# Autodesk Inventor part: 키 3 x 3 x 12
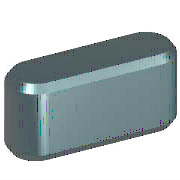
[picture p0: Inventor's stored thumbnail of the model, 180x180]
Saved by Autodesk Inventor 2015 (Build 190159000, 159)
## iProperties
Created: 2012-02
Part Number: 키 3 x 3 x 12
Material: 강철, 연강
Description: 키 및 해당 키홈
Document SubType Name: Modeling
Standard: KS B 1311
Designer: mduedu
Standards Organization: KS
Language: ko-KR
Size Designation: 3 x 3 x 12
Categories: <MemberInstance><Categories><Category DisplayName="샤프트 부품" InternalName="7f7aeb1f-a693-4053-b835-cee3144e0d98" Mnemonic="SHFT"><Category DisplayName="키" Interna
Density: 1 g/cm^3
Appearance: 강철
IsCustomPart: 1
Author: mduedu
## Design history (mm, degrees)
workplane "Work Plane1"
workplane "Work Plane2"
sketch "스케치1"
  geometry: L1 (1.5, 1.5)-(10.5, 1.5); L2 (10.5, -1.5)-(1.5, -1.5); L3 (0, 9.4)-(0, -7.4) reference; L4 (-5, 0)-(30, 0) reference; L5 (12, 0)-(12, 7); A1 r 1.5 centre (1.5, 0) between (1.5, 1.5) and (1.5, -1.5); A2 r 1.5 centre (10.5, 0) between (10.5, -1.5) and (10.5, 1.5)
  constraints: 6 end point, 5 point on circle, 4 tangent, 3 point on line, 2 centre point, 1 horizontal, 1 parallel, 1 perpendicular
  dimensions: "d0" = 1.5 radius of A1 (= 0.5 x PB); "d13" = 1.5 radius of A2 (= 0.5 x PB); "d14" = 12 distance between parallel lines of L5 L3 (= NLG)
extrude "본체1" new body sketch "스케치1" taper "d3" = 0 deg; stored distance "d4" = 10
workplane "Work Plane3"
body "Solid1"
chamfer "모따기1" distance "d8" = 0.25 (= PHH); stored, may be unused: second distance "d9" = 0.25 (= PHH), angle "d15" = 45 deg
other parameters: "d1" = -1.8 (= -PNT), "d2" = 1.2 (= PH - PNT), "NLG" = 12 [user parameter; used in 3 equation terms], "PB" = 3 [user parameter; used in 2 equation terms], "PNT" = 1.8 [user parameter; used in 2 equation terms], "PH" = 3 [user parameter; used in 1 equation term], "PHH" = 0.25 [user parameter; used in 2 equation terms], "d10" = 0, "d16" = 0, "d17" = 0, "d18" = 0, "WDMIN" = 8 [user parameter], "PLB2" = 12 (= NLG) [user parameter], "PLB1" = 12 (= NLG) [user parameter], "RR" = 0.08 [user parameter], "PUEB" = 1.4 [user parameter]
